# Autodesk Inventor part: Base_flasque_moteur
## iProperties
Shininess: 64.0
Length Units: 11269
Angle Units: 11279
Time Units: 11290
Mass Units: 11283
Length Display Precision: 3
Angle Display Precision: 2
Compacted: True
Part Number: Base_flasque_moteur
Document SubType Name: Modeling
Created: 2008-02
Material: Acier inoxydable, austénitique
Designer: Pascal
Density: 0.0
Volumn: 0.0
Area: 0.0
PropertySet Name: Model Information
Control State: 0
Master: False
Checked Out: False
MATIERE_PIECE: X2CrNi 18-11
OBSERVATIONS: Ø715 ep. 20
DESIGNATION: Base flasque moteur
Author: Pascal
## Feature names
1. Extrusion1
2. Extrusion2
3. Réseau circulaire1 [Circular Pattern]
4. Extrusion3
5. Extrusion4
6. Extrusion5
7. Réseau circulaire2 [Circular Pattern]
